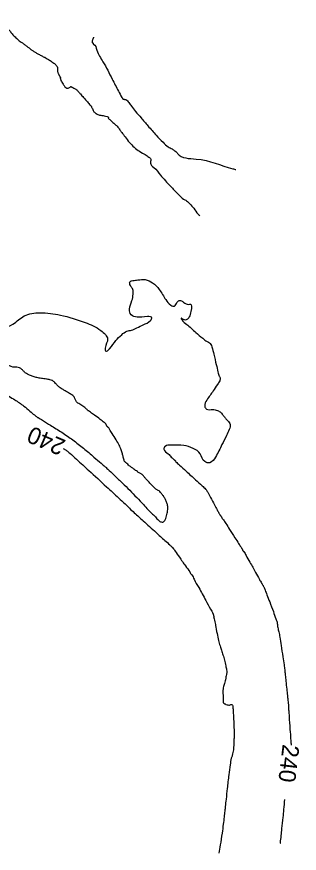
# Model space of a CAD drawing. Extents: x -478102 to -473059, y -1117705 to -1114104.
# Drawn here: x -476686.2 to -476619.3, y -1115538.8 to -1115340.6 of the extents above; entities that cross this region are included whole.
import ezdxf

# ---------------------------------------------------------------- set-up
doc = ezdxf.new("R2010")
doc.units = 0
for name, color, linetype in [('Vrstevnice_hlavni', 7, 'Continuous'), ('Vrstevnice_popis', 7, 'Continuous'), ('Vrstevnice_vedlejsi', 7, 'Continuous')]:
    doc.layers.add(name, color=color, linetype=linetype)

msp = doc.modelspace()

# ---------------------------------------------------------------- linework, layer by layer
at = {"layer": 'Vrstevnice_hlavni'}
for points in [[(-476694.514, -1115412.045), (-476691.345, -1115414.305), (-476689.393, -1115414.404), (-476687.074, -1115413.471), (-476684.386, -1115411.507), (-476680.639, -1115410.789), (-476675.832, -1115411.318), (-476669.965, -1115413.094), (-476666.242, -1115414.989), (-476664.663, -1115417.004), (-476665.227, -1115419.137), (-476665.089, -1115419.907), (-476664.248, -1115419.314), (-476662.704, -1115417.357), (-476661.315, -1115415.966), (-476660.082, -1115415.141), (-476659.004, -1115414.882), (-476657.715, -1115414.37), (-476656.214, -1115413.603), (-476654.502, -1115412.584), (-476654.173, -1115411.949), (-476655.227, -1115411.7), (-476657.665, -1115411.836), (-476659.089, -1115411.249), (-476659.5, -1115409.939), (-476658.898, -1115407.906), (-476658.635, -1115406.336), (-476658.712, -1115405.23), (-476659.128, -1115404.587), (-476659.376, -1115404.062), (-476659.454, -1115403.656), (-476659.363, -1115403.369), (-476658.713, -1115403.152), (-476657.505, -1115403.005), (-476655.737, -1115402.929), (-476654.049, -1115403.68), (-476652.439, -1115405.258), (-476650.909, -1115407.664), (-476649.699, -1115408.979), (-476648.811, -1115409.202), (-476648.243, -1115408.335), (-476647.687, -1115407.906), (-476647.144, -1115407.917), (-476646.613, -1115408.367), (-476646.085, -1115408.656), (-476645.559, -1115408.783), (-476645.036, -1115408.749), (-476644.807, -1115409.192), (-476644.871, -1115410.112), (-476645.229, -1115411.508), (-476645.747, -1115412.298), (-476646.426, -1115412.48), (-476647.265, -1115412.055), (-476647.104, -1115412.408), (-476645.942, -1115413.539), (-476643.78, -1115415.447), (-476642.16, -1115416.803), (-476641.083, -1115417.608), (-476640.548, -1115417.86), (-476640.014, -1115418.854), (-476639.481, -1115420.589), (-476638.949, -1115423.066), (-476638.54, -1115424.799), (-476638.253, -1115425.79), (-476638.09, -1115426.037), (-476638.013, -1115426.299), (-476638.023, -1115426.577), (-476638.119, -1115426.871), (-476638.676, -1115427.78), (-476639.692, -1115429.303), (-476641.169, -1115431.442), (-476641.68, -1115432.882), (-476641.226, -1115433.623), (-476639.806, -1115433.667), (-476638.674, -1115433.934), (-476637.83, -1115434.426), (-476637.273, -1115435.142), (-476636.759, -1115435.768), (-476636.288, -1115436.304), (-476635.858, -1115436.75), (-476635.644, -1115437.255), (-476635.645, -1115437.82), (-476635.862, -1115438.443), (-476636.512, -1115439.842), (-476637.596, -1115442.015), (-476639.114, -1115444.962), (-476640.476, -1115446.306), (-476641.681, -1115446.046), (-476642.729, -1115444.182), (-476644.383, -1115442.907), (-476646.642, -1115442.22), (-476649.507, -1115442.122), (-476651.073, -1115442.418), (-476651.342, -1115443.108), (-476650.314, -1115444.192), (-476649.587, -1115444.95), (-476649.162, -1115445.383)], [(-476675.172, -1115442.891), (-476674.626, -1115443.23), (-476674.326, -1115443.444), (-476673.998, -1115443.703), (-476673.643, -1115444.006), (-476672.012, -1115445.487), (-476669.106, -1115448.147), (-476664.923, -1115451.985), (-476662.048, -1115454.626), (-476660.479, -1115456.072), (-476660.217, -1115456.321), (-476659.967, -1115456.568), (-476659.729, -1115456.815), (-476659.502, -1115457.059), (-476658.339, -1115458.137), (-476656.24, -1115460.049), (-476653.205, -1115462.795), (-476651.104, -1115464.702), (-476649.939, -1115465.77), (-476649.71, -1115466), (-476649.538, -1115466.17), (-476649.425, -1115466.28), (-476649.37, -1115466.33), (-476649.316, -1115466.382), (-476649.261, -1115466.437), (-476649.207, -1115466.495), (-476648.681, -1115467.234), (-476647.683, -1115468.656), (-476646.214, -1115470.761), (-476645.234, -1115472.165), (-476644.744, -1115472.867), (-476644.743, -1115472.868), (-476644.742, -1115472.869), (-476644.741, -1115472.87), (-476644.189, -1115473.878), (-476643.085, -1115475.892), (-476641.429, -1115478.913), (-476640.313, -1115480.954), (-476639.736, -1115482.014), (-476639.7, -1115482.095), (-476639.658, -1115482.232), (-476639.61, -1115482.426), (-476639.555, -1115482.676), (-476639.518, -1115482.842), (-476639.5, -1115482.925), (-476639.501, -1115482.924), (-476639.378, -1115483.565), (-476639.133, -1115484.846), (-476638.766, -1115486.769), (-476638.404, -1115488.387), (-476638.048, -1115489.699), (-476637.698, -1115490.706), (-476637.354, -1115491.828), (-476637.017, -1115493.063), (-476636.686, -1115494.413), (-476636.484, -1115495.376), (-476636.411, -1115495.954), (-476636.467, -1115496.145), (-476636.546, -1115496.498), (-476636.648, -1115497.014), (-476636.772, -1115497.691), (-476636.911, -1115498.298), (-476637.064, -1115498.836), (-476637.232, -1115499.305), (-476637.332, -1115499.88), (-476637.364, -1115500.562), (-476637.328, -1115501.351), (-476637.305, -1115501.916), (-476637.295, -1115502.255), (-476637.299, -1115502.369), (-476637.302, -1115502.476), (-476637.305, -1115502.575), (-476637.308, -1115502.666), (-476637.314, -1115502.785), (-476637.323, -1115502.931), (-476637.335, -1115503.105), (-476637.185, -1115503.279), (-476636.871, -1115503.453), (-476636.395, -1115503.627), (-476635.985, -1115503.7), (-476635.641, -1115503.673), (-476635.364, -1115503.545), (-476635.163, -1115503.629), (-476635.036, -1115503.926), (-476634.985, -1115504.435), (-476634.924, -1115505.348), (-476634.853, -1115506.665), (-476634.773, -1115508.386), (-476634.73, -1115509.857), (-476634.725, -1115511.078), (-476634.757, -1115512.048), (-476634.794, -1115512.909), (-476634.835, -1115513.661), (-476634.88, -1115514.304), (-476634.986, -1115514.959), (-476635.152, -1115515.626)], [(-476649.162, -1115445.383), (-476649.04, -1115445.49), (-476648.941, -1115445.572), (-476648.865, -1115445.628), (-476648.813, -1115445.658), (-476648.733, -1115445.739), (-476648.624, -1115445.87), (-476648.485, -1115446.051), (-476647.64, -1115446.857), (-476646.086, -1115448.29), (-476643.825, -1115450.347), (-476642.282, -1115451.76), (-476641.459, -1115452.527), (-476641.355, -1115452.649), (-476640.975, -1115453.309), (-476640.32, -1115454.508), (-476639.39, -1115456.245), (-476638.725, -1115457.487), (-476638.325, -1115458.232), (-476638.189, -1115458.482), (-476638.072, -1115458.678), (-476637.972, -1115458.818), (-476637.89, -1115458.904), (-476637.818, -1115458.998), (-476637.755, -1115459.099), (-476637.701, -1115459.209), (-476637.598, -1115459.369), (-476637.444, -1115459.58), (-476637.241, -1115459.842), (-476636.687, -1115460.676), (-476635.784, -1115462.084), (-476634.529, -1115464.064), (-476633.647, -1115465.448), (-476633.135, -1115466.236), (-476632.994, -1115466.428), (-476632.881, -1115466.609), (-476632.795, -1115466.779), (-476632.737, -1115466.94), (-476632.656, -1115467.089), (-476632.553, -1115467.228), (-476632.427, -1115467.356), (-476631.9, -1115468.24), (-476630.973, -1115469.88), (-476629.645, -1115472.275), (-476628.725, -1115473.931), (-476628.212, -1115474.846), (-476628.107, -1115475.022), (-476628.006, -1115475.185), (-476627.909, -1115475.337), (-476627.816, -1115475.477), (-476627.693, -1115475.718), (-476627.539, -1115476.06), (-476627.355, -1115476.503), (-476626.941, -1115477.57), (-476626.298, -1115479.261), (-476625.426, -1115481.577), (-476624.826, -1115483.283), (-476624.499, -1115484.379), (-476624.444, -1115484.865), (-476624.364, -1115485.358), (-476624.256, -1115485.859), (-476624.123, -1115486.367), (-476623.9, -1115487.607), (-476623.587, -1115489.58), (-476623.185, -1115492.284), (-476622.903, -1115494.208), (-476622.739, -1115495.352), (-476622.695, -1115495.716), (-476622.601, -1115496.605), (-476622.457, -1115498.019), (-476622.264, -1115499.957), (-476622.111, -1115501.417), (-476622, -1115502.399), (-476621.93, -1115502.903), (-476621.882, -1115503.325), (-476621.857, -1115503.666), (-476621.854, -1115503.924), (-476621.783, -1115505.089), (-476621.644, -1115507.16), (-476621.437, -1115510.137), (-476621.299, -1115512.128), (-476621.23, -1115513.132), (-476621.229, -1115513.166)], [(-476635.152, -1115515.626), (-476635.379, -1115516.305), (-476635.654, -1115517.842), (-476635.977, -1115520.236), (-476636.347, -1115523.487), (-476636.628, -1115525.999), (-476636.819, -1115527.773), (-476636.921, -1115528.807), (-476637.078, -1115530.196), (-476637.292, -1115531.938), (-476637.562, -1115534.035), (-476638.001, -1115536.851), (-476638.334, -1115538.813)], [(-476623.777, -1115536.473), (-476623.758, -1115536.31), (-476623.38, -1115532.975), (-476623.098, -1115530.352), (-476622.914, -1115528.44), (-476622.74, -1115526.038)]]:
    msp.add_spline(points, degree=3, dxfattribs=at)
at = {"layer": 'Vrstevnice_vedlejsi'}
for points in [[(-476728.754, -1115285.648), (-476728.614, -1115285.758), (-476728.25, -1115286.052), (-476727.589, -1115286.586), (-476726.634, -1115287.359), (-476725.642, -1115288.167), (-476724.613, -1115289.007), (-476723.546, -1115289.882), (-476722.727, -1115290.571), (-476722.156, -1115291.074), (-476721.831, -1115291.391), (-476721.403, -1115291.775), (-476720.871, -1115292.226), (-476720.236, -1115292.743), (-476719.68, -1115293.23), (-476719.202, -1115293.684), (-476718.803, -1115294.107), (-476718.37, -1115294.55), (-476717.901, -1115295.012), (-476717.398, -1115295.493), (-476716.583, -1115296.223), (-476715.457, -1115297.202), (-476714.019, -1115298.428), (-476712.743, -1115299.556), (-476711.629, -1115300.583), (-476710.677, -1115301.512), (-476709.729, -1115302.409), (-476708.786, -1115303.273), (-476707.847, -1115304.106), (-476706.869, -1115304.994), (-476705.852, -1115305.936), (-476704.795, -1115306.933), (-476704.074, -1115307.613), (-476703.686, -1115307.976), (-476703.632, -1115308.023), (-476703.077, -1115308.425), (-476702.02, -1115309.182), (-476700.462, -1115310.294), (-476699.402, -1115311.056), (-476698.841, -1115311.466), (-476698.779, -1115311.526), (-476698.688, -1115311.988), (-476698.567, -1115312.853), (-476698.417, -1115314.12), (-476698.321, -1115315.088), (-476698.279, -1115315.756), (-476698.29, -1115316.124), (-476698.458, -1115316.537), (-476698.78, -1115316.993), (-476699.259, -1115317.493), (-476699.552, -1115318.079), (-476699.659, -1115318.751), (-476699.581, -1115319.508), (-476699.664, -1115320.515), (-476699.91, -1115321.771), (-476700.317, -1115323.277), (-476700.41, -1115324.607), (-476700.19, -1115325.76), (-476699.655, -1115326.736), (-476699.131, -1115327.678), (-476698.617, -1115328.586), (-476698.112, -1115329.459), (-476697.773, -1115330.052), (-476697.599, -1115330.366), (-476697.59, -1115330.399), (-476697.582, -1115330.473), (-476697.577, -1115330.587), (-476697.574, -1115330.742), (-476697.544, -1115330.943), (-476697.487, -1115331.188), (-476697.404, -1115331.477), (-476697.298, -1115331.7), (-476697.168, -1115331.856), (-476697.015, -1115331.945), (-476696.809, -1115332.207), (-476696.549, -1115332.641), (-476696.235, -1115333.249), (-476695.912, -1115333.908), (-476695.578, -1115334.619), (-476695.234, -1115335.381), (-476694.868, -1115336.104), (-476694.481, -1115336.786), (-476694.072, -1115337.428), (-476693.613, -1115338.107), (-476693.102, -1115338.821), (-476692.54, -1115339.572), (-476691.753, -1115340.418), (-476690.74, -1115341.359), (-476689.502, -1115342.395), (-476688.482, -1115343.33), (-476687.682, -1115344.165), (-476687.1, -1115344.899), (-476686.394, -1115345.623), (-476685.565, -1115346.337), (-476684.611, -1115347.04), (-476683.967, -1115347.515), (-476683.635, -1115347.76)], [(-476782.237, -1115320.123), (-476781.894, -1115320.658), (-476781.575, -1115321.206), (-476781.278, -1115321.766), (-476781.004, -1115322.338), (-476780.519, -1115323.233), (-476779.823, -1115324.45), (-476778.917, -1115325.991), (-476778.088, -1115327.415), (-476777.337, -1115328.722), (-476776.664, -1115329.912), (-476776.033, -1115330.843), (-476775.445, -1115331.514), (-476774.901, -1115331.926), (-476774.298, -1115332.797), (-476773.638, -1115334.125), (-476772.919, -1115335.911), (-476772.483, -1115337.259), (-476772.327, -1115338.168), (-476772.453, -1115338.639), (-476772.442, -1115339.19), (-476772.295, -1115339.823), (-476772.01, -1115340.536), (-476771.63, -1115341.381), (-476771.154, -1115342.357), (-476770.581, -1115343.464), (-476769.729, -1115345.262), (-476768.597, -1115347.752), (-476767.186, -1115350.932), (-476765.737, -1115354.067), (-476764.251, -1115357.156), (-476762.728, -1115360.2), (-476761.525, -1115362.664), (-476760.643, -1115364.548), (-476760.08, -1115365.851), (-476759.252, -1115367.612), (-476758.157, -1115369.831), (-476756.797, -1115372.509), (-476755.717, -1115374.638), (-476754.918, -1115376.22), (-476754.4, -1115377.253), (-476753.686, -1115378.773), (-476752.779, -1115380.777), (-476751.676, -1115383.267), (-476750.604, -1115385.569), (-476749.564, -1115387.683), (-476748.555, -1115389.609), (-476747.753, -1115391.107), (-476747.157, -1115392.176), (-476746.769, -1115392.816), (-476745.549, -1115394.316), (-476743.499, -1115396.676), (-476740.618, -1115399.896), (-476738.554, -1115402.201), (-476737.309, -1115403.591), (-476736.881, -1115404.066), (-476736.474, -1115404.475), (-476736.086, -1115404.817), (-476735.719, -1115405.094), (-476734.627, -1115406.069), (-476732.811, -1115407.743), (-476730.271, -1115410.116), (-476728.369, -1115411.818), (-476727.105, -1115412.85), (-476726.48, -1115413.21), (-476724.474, -1115414.254), (-476721.088, -1115415.982), (-476716.321, -1115418.392), (-476712.928, -1115420.107), (-476710.91, -1115421.125), (-476710.266, -1115421.447), (-476708.515, -1115422.06), (-476705.659, -1115422.963), (-476701.696, -1115424.157), (-476698.897, -1115425.025), (-476697.26, -1115425.566), (-476696.787, -1115425.782), (-476695.322, -1115426.55), (-476692.866, -1115427.871), (-476689.419, -1115429.745), (-476686.633, -1115431.41), (-476684.509, -1115432.866), (-476683.045, -1115434.113), (-476681.996, -1115434.986), (-476681.361, -1115435.485), (-476681.14, -1115435.61), (-476680.092, -1115436.253), (-476678.218, -1115437.413), (-476675.517, -1115439.092), (-476672.896, -1115440.911), (-476670.354, -1115442.871), (-476667.892, -1115444.973), (-476666.18, -1115446.439), (-476665.218, -1115447.269), (-476665.006, -1115447.464), (-476664.259, -1115448.17), (-476662.978, -1115449.387)], [(-476668.016, -1115345.514), (-476668.077, -1115345.725), (-476668.139, -1115345.826), (-476668.199, -1115345.988), (-476668.255, -1115346.211), (-476668.309, -1115346.495), (-476668.313, -1115346.694), (-476668.266, -1115346.806), (-476668.17, -1115346.832), (-476668.111, -1115346.875), (-476668.089, -1115346.935), (-476668.104, -1115347.012), (-476668.093, -1115347.072), (-476668.054, -1115347.116), (-476667.988, -1115347.144), (-476667.223, -1115348.54), (-476665.757, -1115351.304), (-476663.592, -1115355.436), (-476662.106, -1115358.258), (-476661.298, -1115359.77), (-476661.17, -1115359.972), (-476661.066, -1115360.108), (-476660.986, -1115360.178), (-476660.93, -1115360.183), (-476660.817, -1115360.2), (-476660.648, -1115360.23), (-476660.422, -1115360.273), (-476660.272, -1115360.304), (-476660.198, -1115360.325), (-476660.2, -1115360.336), (-476660.181, -1115360.36), (-476660.142, -1115360.399), (-476660.082, -1115360.452), (-476660.035, -1115360.497), (-476660.003, -1115360.533), (-476659.984, -1115360.561), (-476659.651, -1115360.992), (-476659.004, -1115361.825), (-476658.043, -1115363.061), (-476656.746, -1115364.624), (-476655.114, -1115366.514), (-476653.146, -1115368.731), (-476651.538, -1115370.381), (-476650.289, -1115371.464), (-476649.4, -1115371.979), (-476648.737, -1115372.416), (-476648.301, -1115372.775), (-476648.091, -1115373.056), (-476643.671, -1115374.353), (-476635.041, -1115376.665), (-476634.272, -1115376.869)], [(-476683.635, -1115347.76), (-476683.613, -1115347.776), (-476683.43, -1115347.915), (-476683.085, -1115348.178), (-476682.578, -1115348.565), (-476682.002, -1115348.951), (-476681.357, -1115349.335), (-476680.642, -1115349.717), (-476680.082, -1115350.009), (-476679.677, -1115350.211), (-476679.426, -1115350.322), (-476678.963, -1115350.594), (-476678.288, -1115351.025), (-476677.401, -1115351.617), (-476676.811, -1115352.178), (-476676.518, -1115352.707), (-476676.522, -1115353.207), (-476676.491, -1115353.617), (-476676.424, -1115353.938), (-476676.323, -1115354.169), (-476676.253, -1115354.329), (-476676.214, -1115354.416), (-476676.207, -1115354.43), (-476676.185, -1115354.463), (-476676.151, -1115354.515), (-476676.103, -1115354.585), (-476676.045, -1115354.678), (-476675.977, -1115354.794), (-476675.9, -1115354.932), (-476675.856, -1115355.034), (-476675.844, -1115355.1), (-476675.866, -1115355.131), (-476675.849, -1115355.25), (-476675.794, -1115355.458), (-476675.7, -1115355.755), (-476675.497, -1115356.148), (-476675.186, -1115356.636), (-476674.765, -1115357.221), (-476674.373, -1115357.542), (-476674.008, -1115357.601), (-476673.671, -1115357.398), (-476673.444, -1115357.265), (-476673.326, -1115357.204), (-476673.32, -1115357.214), (-476673.314, -1115357.222), (-476673.311, -1115357.226), (-476673.309, -1115357.228), (-476673.171, -1115357.301), (-476672.895, -1115357.447), (-476672.483, -1115357.665), (-476672.205, -1115357.811), (-476672.062, -1115357.887), (-476672.053, -1115357.892), (-476672.047, -1115357.896), (-476672.044, -1115357.899), (-476672.044, -1115357.901), (-476672.044, -1115357.904), (-476672.043, -1115357.906), (-476672.042, -1115357.909), (-476671.964, -1115357.994), (-476671.81, -1115358.161), (-476671.579, -1115358.411), (-476671.101, -1115358.942), (-476670.376, -1115359.754), (-476669.404, -1115360.848), (-476668.76, -1115361.587), (-476668.444, -1115361.97), (-476668.456, -1115361.999), (-476668.369, -1115362.207), (-476668.181, -1115362.596), (-476667.893, -1115363.165), (-476667.349, -1115363.61), (-476666.55, -1115363.932), (-476665.495, -1115364.129), (-476664.802, -1115364.304), (-476664.47, -1115364.455), (-476664.499, -1115364.584), (-476664.267, -1115364.89), (-476663.773, -1115365.375), (-476663.019, -1115366.038), (-476662.438, -1115366.597), (-476662.033, -1115367.052), (-476661.802, -1115367.403), (-476661.303, -1115368.081), (-476660.535, -1115369.086), (-476659.499, -1115370.417), (-476658.36, -1115371.566), (-476657.116, -1115372.534), (-476655.769, -1115373.32), (-476654.876, -1115373.935), (-476654.437, -1115374.378), (-476654.451, -1115374.651), (-476654.471, -1115374.9), (-476654.497, -1115375.125), (-476654.529, -1115375.326), (-476653.755, -1115376.338), (-476652.176, -1115378.161)], [(-476652.176, -1115378.161), (-476649.791, -1115380.796), (-476647.966, -1115382.688), (-476646.7, -1115383.839), (-476645.994, -1115384.248), (-476645.181, -1115384.978), (-476644.261, -1115386.031), (-476643.233, -1115387.406), (-476642.857, -1115387.728)], [(-476662.978, -1115449.387), (-476661.162, -1115451.115), (-476659.428, -1115452.833), (-476657.775, -1115454.539), (-476656.203, -1115456.234), (-476655.091, -1115457.422), (-476654.44, -1115458.103), (-476654.248, -1115458.277), (-476653.83, -1115458.682), (-476653.188, -1115459.318), (-476652.32, -1115460.185), (-476651.602, -1115460.342), (-476651.034, -1115459.79), (-476650.616, -1115458.529), (-476650.426, -1115457.411), (-476650.465, -1115456.437), (-476650.734, -1115455.606), (-476651.064, -1115454.853), (-476651.456, -1115454.179), (-476651.91, -1115453.583), (-476652.314, -1115453.147), (-476652.667, -1115452.871), (-476652.971, -1115452.754), (-476653.438, -1115452.391), (-476654.067, -1115451.782), (-476654.86, -1115450.927), (-476655.478, -1115450.245), (-476655.922, -1115449.736), (-476656.193, -1115449.4), (-476656.471, -1115449.126), (-476656.758, -1115448.916), (-476657.052, -1115448.768), (-476657.611, -1115448.399), (-476658.436, -1115447.809), (-476659.525, -1115446.999), (-476660.283, -1115446.343), (-476660.709, -1115445.841), (-476660.803, -1115445.493), (-476660.957, -1115444.947), (-476661.171, -1115444.203), (-476661.444, -1115443.26), (-476661.933, -1115442.141), (-476662.639, -1115440.846), (-476663.561, -1115439.375), (-476664.221, -1115438.364), (-476664.618, -1115437.813), (-476664.752, -1115437.722), (-476664.86, -1115437.596), (-476664.943, -1115437.434), (-476665, -1115437.237), (-476665.492, -1115436.771), (-476666.419, -1115436.037), (-476667.78, -1115435.035), (-476668.702, -1115434.357), (-476669.185, -1115434.005), (-476669.229, -1115433.978), (-476669.39, -1115433.837), (-476669.67, -1115433.583), (-476670.069, -1115433.216), (-476670.505, -1115432.879), (-476670.978, -1115432.571), (-476671.488, -1115432.293), (-476671.875, -1115432.002), (-476672.139, -1115431.697), (-476672.28, -1115431.379), (-476672.413, -1115431.092), (-476672.539, -1115430.834), (-476672.658, -1115430.608), (-476673.107, -1115430.246), (-476673.887, -1115429.751), (-476674.998, -1115429.121), (-476675.882, -1115428.538), (-476676.537, -1115428.001), (-476676.965, -1115427.511), (-476677.317, -1115427.145), (-476677.594, -1115426.903), (-476677.795, -1115426.786), (-476678.319, -1115426.654), (-476679.165, -1115426.506), (-476680.332, -1115426.344), (-476681.381, -1115426.133), (-476682.309, -1115425.874), (-476683.118, -1115425.567), (-476683.832, -1115425.184), (-476684.45, -1115424.726), (-476684.974, -1115424.193), (-476685.537, -1115423.844), (-476686.14, -1115423.68), (-476686.782, -1115423.702), (-476687.474, -1115423.526), (-476688.215, -1115423.152), (-476689.005, -1115422.58), (-476689.612, -1115422.166), (-476690.034, -1115421.909), (-476690.272, -1115421.81), (-476691.16, -1115421.412), (-476692.696, -1115420.715)]]:
    msp.add_spline(points, degree=3, dxfattribs=at)

# ---------------------------------------------------------------- texts
at = {"layer": 'Vrstevnice_popis'}
for rotation, p in [(156.68695, (-476672.98, -1115441.651)), (263.30365, (-476623.038, -1115511.42))]:
    msp.add_text(' 240 ', height=4, rotation=rotation, dxfattribs=at).set_placement(p)

doc.saveas('drawing.dxf')
